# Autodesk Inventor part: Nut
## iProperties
Created: 2002-01
Part Number: Nut
Document SubType Name: Modeling
Designer: ***
Control State: 0
Master: False
Checked Out: False
Shininess: 20.0
Length Units: 11269
Angle Units: 11279
Time Units: 11290
Mass Units: 11283
Length Display Precision: 3
Angle Display Precision: 2
Density: 0.0
Volumn: 0.0
Area: 0.0
PropertySet Name: Model Information
Author: ***
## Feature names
1. Extrusion1
2. Fillet1
3. Extrusion2
